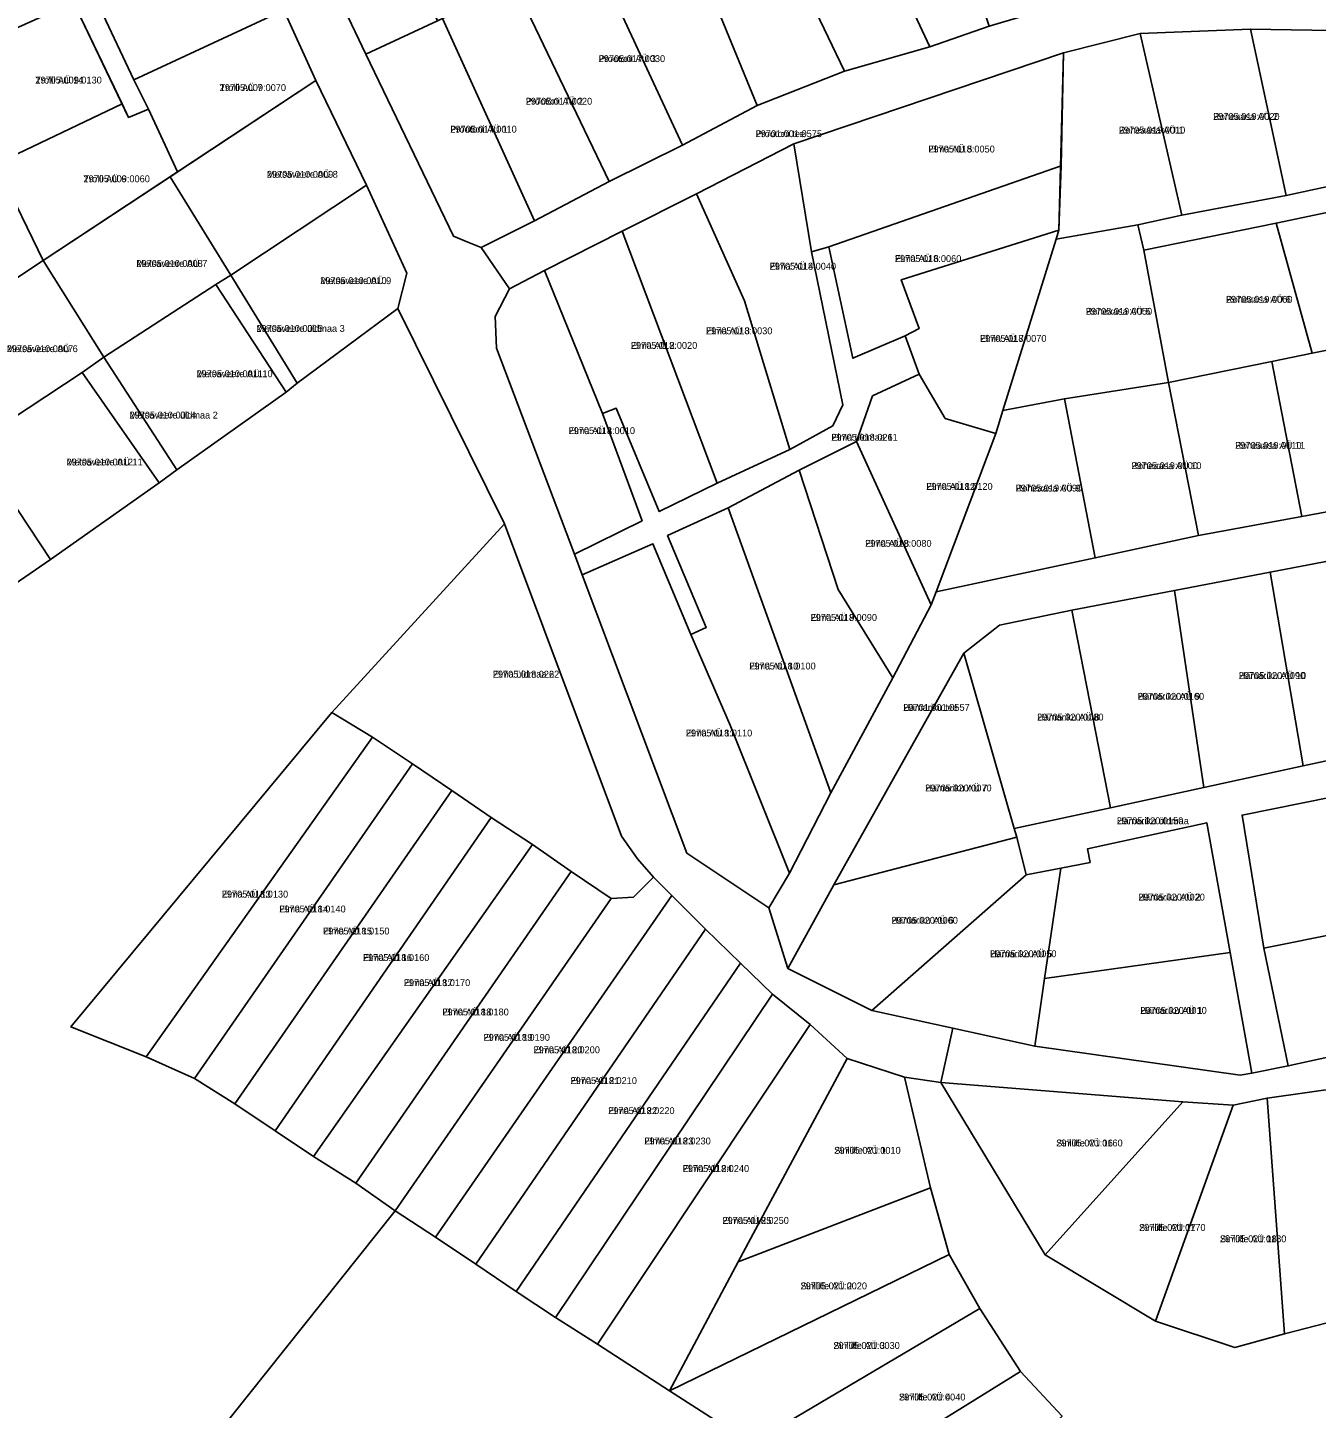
# Model space of a CAD drawing. Extents: x 504287 to 537970, y 6539941 to 6586214.
# Drawn here: x 519273.8 to 519555.2, y 6562734.5 to 6563035.9 of the extents above; entities that cross this region are included whole.
import ezdxf

# ---------------------------------------------------------------- set-up
doc = ezdxf.new("R2010")
doc.units = 0
for name, color, linetype in [('L_AADRESS', 7, 'Continuous'), ('PIIR', 7, 'Continuous'), ('TUNNUS', 7, 'Continuous')]:
    doc.layers.add(name, color=color, linetype=linetype)

msp = doc.modelspace()

# ---------------------------------------------------------------- linework, layer by layer
at = {"layer": 'PIIR'}
for points in [[(519459.04, 6563081.85), (519468.39, 6563083.05), (519483.82, 6563036.19), (519470.82, 6563031.67), (519449.42, 6563077.37)], [(519344.4, 6563077.05), (519363.32, 6563037.32), (519347.72, 6563030.07), (519329.09, 6563069.16), (519328.8, 6563069.8)], [(519449.42, 6563077.37), (519470.82, 6563031.67), (519452.23, 6563026.37), (519431.67, 6563069.12)], [(519415.6, 6563061.64), (519431.67, 6563069.12), (519452.23, 6563026.37), (519433.17, 6563018.85)], [(519415.6, 6563061.64), (519433.17, 6563018.85), (519416.85, 6563010.23), (519396.97, 6563052.98)], [(519288.49, 6563042.57), (519321.26, 6563057.86), (519329.79, 6563039.66), (519297.06, 6563024.45)], [(519396.97, 6563052.98), (519416.85, 6563010.23), (519400.83, 6563002.24), (519380.21, 6563045.18)], [(519380.21, 6563045.18), (519400.83, 6563002.24), (519384.54, 6562993.66), (519364.4, 6563037.83)], [(519379.09, 6562978.83), (519372.84, 6562987.83), (519384.54, 6562993.66), (519400.83, 6563002.24), (519416.85, 6563010.23), (519433.17, 6563018.85), (519452.23, 6563026.37), (519470.82, 6563031.67), (519483.82, 6563036.19), (519500.29, 6563041.06), (519518.28, 6563044.73), (519537.55, 6563044.73), (519555.2, 6563044.87), (519572.77, 6563044.98), (519588.48, 6563045.08), (519591.71, 6563035.32), (519563.15, 6563035.15), (519540.86, 6563035.52), (519516.8, 6563034.6), (519500.02, 6563030.32), (519441.15, 6563010.5), (519419.88, 6562999.55), (519403.66, 6562991.39), (519386.67, 6562982.83)], [(519256.88, 6563027.76), (519256.32, 6563029.03), (519283.83, 6563041.33), (519294.48, 6563019.19), (519266.68, 6563005.97)], [(519300.23, 6563018.09), (519297.06, 6563024.45), (519329.79, 6563039.66), (519336.76, 6563024.33), (519306.55, 6563004.35)], [(519364.4, 6563037.83), (519384.54, 6562993.66), (519372.84, 6562987.83), (519369.94, 6562989.02), (519366.85, 6562990.32), (519347.72, 6563030.07)], [(519499, 6562991.61), (519500.02, 6563030.32), (519516.8, 6563034.6), (519525.83, 6562994.92), (519516.29, 6562992.78), (519498.39, 6562989.65)], [(519516.8, 6563034.6), (519540.86, 6563035.52), (519548.61, 6562999.2), (519525.83, 6562994.92)], [(519540.86, 6563035.52), (519563.15, 6563035.15), (519571.21, 6563004.1), (519548.61, 6562999.2)], [(519445.02, 6562986.88), (519441.15, 6563010.5), (519500.02, 6563030.32), (519499.51, 6563005.68), (519448.77, 6562987.99)], [(519304.95, 6563003.29), (519336.76, 6563024.33), (519347.85, 6563001.45), (519318.18, 6562981.83)], [(519267.83, 6563004.34), (519266.68, 6563005.97), (519294.48, 6563019.19), (519295.89, 6563016.27), (519300.23, 6563018.09), (519306.55, 6563004.35), (519277.21, 6562985.01)], [(519419.88, 6562999.55), (519441.15, 6563010.5), (519445.02, 6562986.88), (519451.83, 6562953.49), (519449.66, 6562948.95), (519440.27, 6562943.74), (519430.4, 6562976.2)], [(519525.83, 6562994.92), (519548.61, 6562999.2), (519571.21, 6563004.1), (519600.31, 6563010.25), (519602.07, 6563004.65), (519575.22, 6562999.24), (519546.44, 6562993.2), (519517.6, 6562987.28), (519516.29, 6562992.78)], [(519468.48, 6562970.17), (519465.42, 6562968.6), (519454, 6562963.69), (519448.77, 6562987.99), (519499.51, 6563005.68), (519499, 6562991.61), (519464.6, 6562980.81)], [(519238.7, 6562990.76), (519243.47, 6562992.78), (519267.83, 6563004.34), (519277.21, 6562985.01), (519250.06, 6562967.02)], [(519277.21, 6562985.01), (519304.95, 6563003.29), (519318.18, 6562981.83), (519314.9, 6562979.78), (519290.46, 6562963.94)], [(519318.18, 6562981.83), (519347.85, 6563001.45), (519356.67, 6562982.27), (519354.71, 6562974.53), (519332.7, 6562958.28)], [(519419.88, 6562999.55), (519430.4, 6562976.2), (519440.27, 6562943.74), (519424.43, 6562936.39), (519403.66, 6562991.39)], [(519546.44, 6562993.2), (519575.22, 6562999.24), (519581.16, 6562970.07), (519568.11, 6562967.58), (519554.35, 6562964.83)], [(519486.81, 6562952.27), (519498.39, 6562989.65), (519516.29, 6562992.78), (519517.6, 6562987.28), (519522.98, 6562958.41), (519500.24, 6562954.85)], [(519517.6, 6562987.28), (519546.44, 6562993.2), (519554.35, 6562964.83), (519545.51, 6562962.97), (519522.98, 6562958.41)], [(519399.4, 6562951.59), (519386.67, 6562982.83), (519403.66, 6562991.39), (519424.43, 6562936.39), (519411.76, 6562930.21), (519402.34, 6562952.79)], [(519468.54, 6562960.23), (519465.42, 6562968.6), (519468.48, 6562970.17), (519464.6, 6562980.81), (519499, 6562991.61), (519498.39, 6562989.65), (519486.81, 6562952.27), (519485.27, 6562947.29), (519474.2, 6562950.55)], [(519426.82, 6562931.01), (519413.59, 6562924.96), (519422.01, 6562904.94), (519418.67, 6562903.37), (519410.38, 6562923.21), (519394.91, 6562916.42), (519393.28, 6562920.91), (519407.99, 6562928.23), (519399.4, 6562951.59), (519402.34, 6562952.79), (519411.76, 6562930.21), (519424.43, 6562936.39), (519440.27, 6562943.74), (519449.66, 6562948.95), (519451.83, 6562953.49), (519445.02, 6562986.88), (519448.77, 6562987.99), (519454, 6562963.69), (519465.42, 6562968.6), (519468.54, 6562960.23), (519458.33, 6562955.46), (519454.83, 6562945.48), (519442.29, 6562939.28)], [(519248.26, 6562965.83), (519277.21, 6562985.01), (519290.46, 6562963.94), (519285.76, 6562960.55), (519262.08, 6562945.02)], [(519318.18, 6562981.83), (519332.7, 6562958.28), (519330.28, 6562956.28), (519314.9, 6562979.78)], [(519375.92, 6562972.8), (519379.09, 6562978.83), (519386.67, 6562982.83), (519399.4, 6562951.59), (519407.99, 6562928.23), (519393.28, 6562920.91), (519376.22, 6562965.91)], [(519290.46, 6562963.94), (519314.9, 6562979.78), (519330.28, 6562956.28), (519306.41, 6562939.33)], [(519545.51, 6562962.97), (519554.35, 6562964.83), (519568.11, 6562967.58), (519575.3, 6562933.4), (519552.04, 6562929.15)], [(519290.46, 6562963.94), (519306.41, 6562939.33), (519302.59, 6562936.49), (519285.76, 6562960.55)], [(519522.98, 6562958.41), (519545.51, 6562962.97), (519552.04, 6562929.15), (519529.47, 6562925.02)], [(519262.08, 6562945.02), (519285.76, 6562960.55), (519302.59, 6562936.49), (519278.84, 6562919.79)], [(519458.33, 6562955.46), (519468.54, 6562960.23), (519474.2, 6562950.55), (519485.27, 6562947.29), (519472.21, 6562912.67), (519471.15, 6562909.87), (519454.83, 6562945.48)], [(519500.24, 6562954.85), (519522.98, 6562958.41), (519529.47, 6562925.02), (519506.95, 6562920.11)], [(519485.27, 6562947.29), (519486.81, 6562952.27), (519500.24, 6562954.85), (519506.95, 6562920.11), (519472.21, 6562912.67)], [(519241.72, 6562923.17), (519240.88, 6562924.25), (519241.61, 6562924.89), (519240.61, 6562926.56), (519238.99, 6562926.6), (519237.82, 6562928.96), (519262.08, 6562945.02), (519278.84, 6562919.79), (519268.79, 6562912.88), (519245.19, 6562918.12)], [(519442.29, 6562939.28), (519454.83, 6562945.48), (519471.15, 6562909.87), (519462.78, 6562893.96), (519450.81, 6562913.22)], [(519439.86, 6562830.5), (519435.67, 6562843.73), (519440.22, 6562851.26), (519449.22, 6562868.82), (519462.78, 6562893.96), (519471.15, 6562909.87), (519472.21, 6562912.67), (519506.95, 6562920.11), (519529.47, 6562925.02), (519552.04, 6562929.15), (519575.3, 6562933.4), (519596.79, 6562937.66), (519622.37, 6562942.94), (519624.67, 6562932.47), (519591.81, 6562926.12), (519564.98, 6562920.78), (519545.12, 6562917), (519524.25, 6562912.98), (519501.82, 6562908.68), (519486.02, 6562905.4), (519478.28, 6562899.31), (519449.85, 6562848.78)], [(519442.29, 6562939.28), (519450.81, 6562913.22), (519462.78, 6562893.96), (519449.22, 6562868.82), (519426.82, 6562931.01)], [(519418.67, 6562903.37), (519422.01, 6562904.94), (519413.59, 6562924.96), (519426.82, 6562931.01), (519449.22, 6562868.82), (519440.22, 6562851.26), (519427.24, 6562883.59)], [(519403.52, 6562859.34), (519407, 6562854.42), (519410.52, 6562850.39), (519406.1, 6562846.02), (519401.29, 6562845.73), (519392.52, 6562851.65), (519384.06, 6562857.55), (519375.08, 6562863.47), (519366.43, 6562869.36), (519357.85, 6562875.17), (519349.17, 6562881), (519340.29, 6562886.38), (519378, 6562927.52)], [(519410.38, 6562923.21), (519418.67, 6562903.37), (519427.24, 6562883.59), (519440.22, 6562851.26), (519435.67, 6562843.73), (519417.8, 6562855.63), (519394.91, 6562916.42)], [(519545.12, 6562917), (519564.98, 6562920.78), (519573.3, 6562879.22), (519552.33, 6562874.74)], [(519524.25, 6562912.98), (519545.12, 6562917), (519552.33, 6562874.74), (519530.64, 6562870)], [(519501.82, 6562908.68), (519524.25, 6562912.98), (519530.64, 6562870), (519510.26, 6562865.53)], [(519478.28, 6562899.31), (519486.02, 6562905.4), (519501.82, 6562908.68), (519510.26, 6562865.53), (519489.27, 6562861.04)], [(519478.28, 6562899.31), (519489.27, 6562861.04), (519489.8, 6562859.17), (519449.85, 6562848.78)], [(519283.29, 6562817.73), (519340.29, 6562886.38), (519349.17, 6562881), (519299.71, 6562811.22)], [(519299.71, 6562811.22), (519349.17, 6562881), (519357.85, 6562875.17), (519310.27, 6562806.5)], [(519310.27, 6562806.5), (519357.85, 6562875.17), (519366.43, 6562869.36), (519319.05, 6562800.92)], [(519319.05, 6562800.92), (519366.43, 6562869.36), (519375.08, 6562863.47), (519327.9, 6562795.05)], [(519539, 6562863.98), (519571.8, 6562870.57), (519577.45, 6562841.67), (519543.75, 6562834.94)], [(519327.9, 6562795.05), (519375.08, 6562863.47), (519384.06, 6562857.55), (519336.28, 6562789.42)], [(519499.47, 6562852.38), (519505.82, 6562853.63), (519505.27, 6562856.63), (519531.3, 6562862.31), (519536.42, 6562833.97), (519495.86, 6562828.33)], [(519336.28, 6562789.42), (519384.06, 6562857.55), (519392.52, 6562851.65), (519345.48, 6562783.59)], [(519439.86, 6562830.5), (519449.85, 6562848.78), (519489.8, 6562859.17), (519491.9, 6562850.94), (519458.18, 6562821.32)], [(519345.48, 6562783.59), (519392.52, 6562851.65), (519401.29, 6562845.73), (519354.1, 6562777.58)], [(519491.9, 6562850.94), (519499.47, 6562852.38), (519495.86, 6562828.33), (519493.79, 6562813.52), (519475.84, 6562817.45), (519458.18, 6562821.32)], [(519354.1, 6562777.58), (519401.29, 6562845.73), (519406.1, 6562846.02), (519410.52, 6562850.39), (519414.5, 6562846.43), (519362.9, 6562771.83)], [(519362.9, 6562771.83), (519414.5, 6562846.43), (519421.86, 6562839.05), (519371.73, 6562765.95)], [(519543.75, 6562834.94), (519577.45, 6562841.67), (519582.34, 6562816.48), (519549.08, 6562809.21)], [(519371.73, 6562765.95), (519421.86, 6562839.05), (519429.47, 6562831.67), (519380.54, 6562759.95)], [(519495.86, 6562828.33), (519536.42, 6562833.97), (519541.15, 6562807.64), (519538.59, 6562807.2), (519493.79, 6562813.52)], [(519380.54, 6562759.95), (519429.47, 6562831.67), (519436.45, 6562824.86), (519389.08, 6562754.32)], [(519389.08, 6562754.32), (519436.45, 6562824.86), (519444.68, 6562818.27), (519398.3, 6562748.47)], [(519398.3, 6562748.47), (519444.68, 6562818.27), (519452.8, 6562810.81), (519428.99, 6562766.44), (519414, 6562738.26)], [(519452.8, 6562810.81), (519465.32, 6562806.79), (519470.95, 6562782.64), (519428.99, 6562766.44)], [(519473.24, 6562805.59), (519526.06, 6562801.35), (519496.01, 6562767.99)], [(519544.48, 6562802.17), (519561.47, 6562804.58), (519573.38, 6562757.21), (519548.25, 6562750.73)], [(519526.06, 6562801.35), (519537.05, 6562800.62), (519520.13, 6562753.47), (519496.01, 6562767.99)], [(519537.05, 6562800.62), (519544.48, 6562802.17), (519548.25, 6562750.73), (519537.45, 6562747.73), (519520.13, 6562753.47)], [(519428.99, 6562766.44), (519470.95, 6562782.64), (519475.03, 6562768.08), (519414, 6562738.26)], [(519354.1, 6562777.58), (519362.9, 6562771.83), (519371.73, 6562765.95), (519380.54, 6562759.95), (519389.08, 6562754.32), (519398.3, 6562748.47), (519414, 6562738.26), (519431.92, 6562726.8), (519448.04, 6562716.09), (519467.56, 6562703.15), (519485.1, 6562691.61), (519503.5, 6562678.77), (519522.66, 6562666.46), (519541.12, 6562654.31), (519563.38, 6562640.11), (519586.21, 6562624.97), (519470.28, 6562430.96), (519357.09, 6562234.09), (519226.17, 6562256.12), (519120.43, 6562250.63), (519020.18, 6562252.3), (519036.8, 6562302.12), (518991.5, 6562322.94)], [(519414, 6562738.26), (519475.03, 6562768.08), (519481.72, 6562756.29), (519431.92, 6562726.8)], [(519431.92, 6562726.8), (519481.72, 6562756.29), (519490.66, 6562742.52), (519448.04, 6562716.09)], [(519448.04, 6562716.09), (519490.66, 6562742.52), (519499.7, 6562732.76), (519467.56, 6562703.15)]]:
    msp.add_lwpolyline(points, close=True, dxfattribs=at)
for points in [[(519329.09, 6563069.16), (519347.72, 6563030.07), (519366.85, 6562990.32), (519369.94, 6562989.02), (519372.84, 6562987.83), (519379.09, 6562978.83), (519375.92, 6562972.8), (519376.22, 6562965.91), (519393.28, 6562920.91), (519394.91, 6562916.42), (519417.8, 6562855.63), (519435.67, 6562843.73), (519439.86, 6562830.5), (519458.18, 6562821.32), (519475.84, 6562817.45), (519473.24, 6562805.59), (519465.32, 6562806.79), (519452.8, 6562810.81), (519444.68, 6562818.27), (519436.45, 6562824.86), (519429.47, 6562831.67), (519421.86, 6562839.05), (519414.5, 6562846.43), (519410.52, 6562850.39), (519407, 6562854.42), (519403.52, 6562859.34), (519378, 6562927.52), (519354.71, 6562974.53), (519356.67, 6562982.27), (519347.85, 6563001.45), (519336.76, 6563024.33), (519329.79, 6563039.66)], [(519267.25, 6563039.05), (519285.2, 6563047.67), (519318.61, 6563063.16), (519321.26, 6563057.86), (519288.49, 6563042.57), (519297.06, 6563024.45), (519300.23, 6563018.09), (519295.89, 6563016.27), (519283.83, 6563041.33), (519256.32, 6563029.03)], [(519268.79, 6562912.88), (519278.84, 6562919.79), (519302.59, 6562936.49), (519306.41, 6562939.33), (519330.28, 6562956.28), (519332.7, 6562958.28), (519354.71, 6562974.53), (519378, 6562927.52), (519340.29, 6562886.38), (519283.29, 6562817.73), (519299.71, 6562811.22), (519310.27, 6562806.5), (519319.05, 6562800.92), (519327.9, 6562795.05), (519336.28, 6562789.42), (519345.48, 6562783.59), (519354.1, 6562777.58), (518991.5, 6562322.94)], [(519571.8, 6562870.57), (519539, 6562863.98), (519543.75, 6562834.94), (519549.08, 6562809.21), (519541.15, 6562807.64), (519536.42, 6562833.97), (519531.3, 6562862.31), (519505.27, 6562856.63), (519505.82, 6562853.63), (519499.47, 6562852.38), (519491.9, 6562850.94), (519489.8, 6562859.17), (519489.27, 6562861.04), (519510.26, 6562865.53), (519530.64, 6562870), (519552.33, 6562874.74), (519573.3, 6562879.22)], [(519561.47, 6562804.58), (519544.48, 6562802.17), (519537.05, 6562800.62), (519526.06, 6562801.35), (519473.24, 6562805.59), (519475.84, 6562817.45), (519493.79, 6562813.52), (519538.59, 6562807.2), (519541.15, 6562807.64), (519549.08, 6562809.21), (519582.34, 6562816.48)], [(519499.7, 6562732.76), (519490.66, 6562742.52), (519481.72, 6562756.29), (519475.03, 6562768.08), (519470.95, 6562782.64), (519465.32, 6562806.79), (519473.24, 6562805.59), (519496.01, 6562767.99), (519520.13, 6562753.47), (519537.45, 6562747.73), (519548.25, 6562750.73), (519573.38, 6562757.21), (519585.57, 6562758.19), (519594.1, 6562755.96), (519602.25, 6562751.12), (519608.84, 6562744.5), (519613.18, 6562736.37), (519616.08, 6562723.7)]]:
    msp.add_lwpolyline(points, dxfattribs=at)

# ---------------------------------------------------------------- texts
at = {"layer": 'L_AADRESS'}
for s, p in [('Prootoni AÜ 3', (519398.53, 6563028.33)), ('Trolli AÜ 14', (519275.53, 6563023.65)), ('Trolli AÜ 7', (519315.76, 6563022.01)), ('Prootoni AÜ 2', (519382.61, 6563019.03)), ('Roheaasa AÜ 2', (519532.7, 6563015.71)), ('Prootoni AÜ 1', (519366.13, 6563012.93)), ('Prootoni tee', (519432.79, 6563011.95)), ('Roheaasa AÜ 1', (519512.11, 6563012.73)), ('Elma AÜ 5', (519470.52, 6563008.6)), ('Metsaveere AÜ 8', (519326.07, 6563003.08)), ('Trolli AÜ 6', (519286.03, 6563002.1)), ('Elma AÜ 6', (519463.21, 6562984.69)), ('Metsaveere AÜ 7', (519297.58, 6562983.62)), ('Elma AÜ 4', (519435.86, 6562983.02)), ('Metsaveere AÜ 9', (519337.73, 6562979.87)), ('Roheaasa AÜ 6', (519535.51, 6562975.8)), ('Roheaasa AÜ 5', (519504.89, 6562973.18)), ('Metsaveere üldmaa 3', (519323.8, 6562969.45)), ('Elma AÜ 3', (519421.96, 6562968.92)), ('Elma AÜ 7', (519481.8, 6562967.26)), ('Metsaveere AÜ 6', (519269.29, 6562965.02)), ('Elma AÜ 2', (519405.55, 6562965.74)), ('Metsaveere AÜ 10', (519310.72, 6562959.55)), ('Metsaveere üldmaa 2', (519296.08, 6562950.53)), ('Elma AÜ 1', (519391.96, 6562947.13)), ('Elma üldmaa 1', (519449.33, 6562945.68)), ('Roheaasa AÜ 11', (519537.51, 6562943.92)), ('Metsaveere AÜ 11', (519282.34, 6562940.28)), ('Roheaasa AÜ 10', (519514.86, 6562939.49)), ('Elma AÜ 12', (519470.05, 6562934.96)), ('Roheaasa AÜ 9', (519489.58, 6562934.6)), ('Elma AÜ 8', (519456.72, 6562922.53)), ('Elma AÜ 9', (519444.8, 6562906.35)), ('Elma AÜ 10', (519431.41, 6562895.75)), ('Elma üldmaa 2', (519375.41, 6562893.97)), ('Hämariku AÜ 10', (519538.29, 6562893.68)), ('Hämariku AÜ 9', (519516.23, 6562889.14)), ('Hämariku tee', (519465.04, 6562886.72)), ('Hämariku AÜ 8', (519494.27, 6562884.61)), ('Elma AÜ 11', (519417.56, 6562881.13)), ('Hämariku AÜ 7', (519469.82, 6562869.13)), ('Hämariku üldmaa', (519511.68, 6562861.97)), ('Elma AÜ 13', (519316.23, 6562845.96)), ('Hämariku AÜ 2', (519516.39, 6562845.32)), ('Elma AÜ 14', (519328.78, 6562842.72)), ('Hämariku AÜ 6', (519462.46, 6562840.25)), ('Elma AÜ 15', (519338.35, 6562837.91)), ('Elma AÜ 16', (519347.06, 6562832.12)), ('Hämariku AÜ 5', (519483.99, 6562832.95)), ('Elma AÜ 17', (519355.98, 6562826.64)), ('Elma AÜ 18', (519364.4, 6562820.24)), ('Hämariku AÜ 1', (519516.8, 6562820.58)), ('Elma AÜ 19', (519373.38, 6562814.7)), ('Elma AÜ 20', (519384.3, 6562811.98)), ('Elma AÜ 21', (519392.38, 6562805.26)), ('Elma AÜ 22', (519400.6, 6562798.7)), ('Elma AÜ 23', (519408.5, 6562792.08)), ('Sinilille AÜ 16', (519498.44, 6562791.64)), ('Sinilille AÜ 1', (519449.97, 6562790.04)), ('Elma AÜ 24', (519416.88, 6562786.07)), ('Elma AÜ 25', (519425.55, 6562774.73)), ('Sinilille AÜ 17', (519516.53, 6562773.2)), ('Sinilille AÜ 18', (519534.19, 6562770.73)), ('Sinilille AÜ 2', (519442.61, 6562760.45)), ('Sinilille AÜ 3', (519449.78, 6562747.44)), ('Sinilille AÜ 4', (519464.11, 6562736.19))]:
    msp.add_text(s, height=1.5, dxfattribs=at).set_placement(p)
at = {"layer": 'TUNNUS'}
for s, p in [('29705:017:0030', (519398.53, 6563028.33)), ('29705:009:0130', (519275.53, 6563023.65)), ('29705:009:0070', (519315.76, 6563022.01)), ('29705:017:0020', (519382.61, 6563019.03)), ('29705:019:0020', (519532.7, 6563015.71)), ('29705:017:0010', (519366.13, 6563012.93)), ('29701:001:0575', (519432.79, 6563011.95)), ('29705:019:0010', (519512.11, 6563012.73)), ('29705:018:0050', (519470.52, 6563008.6)), ('29705:010:0009', (519326.07, 6563003.08)), ('29705:009:0060', (519286.03, 6563002.1)), ('29705:010:0008', (519297.58, 6562983.62)), ('29705:018:0040', (519435.86, 6562983.02)), ('29705:018:0060', (519463.21, 6562984.69)), ('29705:010:0010', (519337.73, 6562979.87)), ('29705:019:0060', (519535.51, 6562975.8)), ('29705:019:0050', (519504.89, 6562973.18)), ('29705:010:0015', (519323.8, 6562969.45)), ('29705:018:0030', (519421.96, 6562968.92)), ('29705:018:0070', (519481.8, 6562967.26)), ('29705:010:0007', (519269.29, 6562965.02)), ('29705:018:0020', (519405.55, 6562965.74)), ('29705:010:0011', (519310.72, 6562959.55)), ('29705:010:0014', (519296.08, 6562950.53)), ('29705:018:0010', (519391.96, 6562947.13)), ('29705:018:0261', (519449.33, 6562945.68)), ('29705:019:0110', (519537.51, 6562943.92)), ('29705:010:0012', (519282.34, 6562940.28)), ('29705:019:0100', (519514.86, 6562939.49)), ('29705:018:0120', (519470.05, 6562934.96)), ('29705:019:0090', (519489.58, 6562934.6)), ('29705:018:0080', (519456.72, 6562922.53)), ('29705:018:0090', (519444.8, 6562906.35)), ('29705:018:0100', (519431.41, 6562895.75)), ('29705:018:0262', (519375.41, 6562893.97)), ('29705:020:0090', (519538.29, 6562893.68)), ('29705:020:0160', (519516.23, 6562889.14)), ('29701:001:0557', (519465.04, 6562886.72)), ('29705:020:0080', (519494.27, 6562884.61)), ('29705:018:0110', (519417.56, 6562881.13)), ('29705:020:0070', (519469.82, 6562869.13)), ('29705:020:0150', (519511.68, 6562861.97)), ('29705:018:0130', (519316.23, 6562845.96)), ('29705:020:0020', (519516.39, 6562845.32)), ('29705:018:0140', (519328.78, 6562842.72)), ('29705:020:0060', (519462.46, 6562840.25)), ('29705:018:0150', (519338.35, 6562837.91)), ('29705:018:0160', (519347.06, 6562832.12)), ('29705:020:0050', (519483.99, 6562832.95)), ('29705:018:0170', (519355.98, 6562826.64)), ('29705:018:0180', (519364.4, 6562820.24)), ('29705:020:0010', (519516.8, 6562820.58)), ('29705:018:0190', (519373.38, 6562814.7)), ('29705:018:0200', (519384.3, 6562811.98)), ('29705:018:0210', (519392.38, 6562805.26)), ('29705:018:0220', (519400.6, 6562798.7)), ('29705:018:0230', (519408.5, 6562792.08)), ('29705:021:0010', (519449.97, 6562790.04)), ('29705:021:0160', (519498.44, 6562791.64)), ('29705:018:0240', (519416.88, 6562786.07)), ('29705:018:0250', (519425.55, 6562774.73)), ('29705:021:0170', (519516.53, 6562773.2)), ('29705:021:0180', (519534.19, 6562770.73)), ('29705:021:0020', (519442.61, 6562760.45)), ('29705:021:0030', (519449.78, 6562747.44)), ('29705:021:0040', (519464.11, 6562736.19))]:
    msp.add_text(s, height=1.5, dxfattribs=at).set_placement(p)

doc.saveas('drawing.dxf')
